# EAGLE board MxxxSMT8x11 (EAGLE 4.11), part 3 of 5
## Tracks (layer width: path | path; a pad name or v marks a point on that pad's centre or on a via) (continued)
GND4  (via drill 0.61) (continued)
  Bottom 0.381: 166.12,120.65 165.35,120.65 164.34,121.67 C100.2 163.32,122.17 157.99,122.17 C103.2 | 166.12,120.65 173.74,120.65 174.75,121.67 C96.2 175.77,121.67 176.02,121.41 179.07,121.41 179.83,120.65 187.96,120.65 188.09,120.78 | 224.66,120.78 224.54,120.65 214.88,120.65 214.76,120.78 | 224.66,120.78 225.55,121.67 C85.2 | 214.76,120.78 213.87,121.67 C88.2 | 200.79,120.78 200.91,120.65 214.63,120.65 214.76,120.78 | 200.79,120.78 199.9,121.67 C90.2 | 188.09,120.78 188.21,120.65 200.66,120.65 200.79,120.78 | 188.09,120.78 187.2,121.67 C93.2 | U$15.C2 242.57,118.62 240.54,120.65 224.79,120.65 224.66,120.78 | v175.51,73.91 183.64,73.91 R20.1 184.4,73.15 184.4,71.63 R17.1 | v241.55,77.47 240.54,78.49 224.03,78.49 223.77,78.74 v223.52,78.99 v214.63,78.99 214.38,78.74 v200.66,78.74 200.41,78.49 199.9,77.98 187.96,77.98 v187.71,77.72 187.45,77.98 187.2,78.23 177.29,78.23 177.04,78.49 165.1,78.49 161.54,82.04 160.27,82.04 v160.02,82.3 160.02,85.85 159,85.85 157.73,87.12 157.73,88.39 C105.2 157.99,89.15 163.32,89.15 C102.2 164.34,88.65 165.35,87.63 176.53,87.63 176.66,87.76 | C104.2 157.99,105.66 163.32,105.66 C101.2 164.34,105.16 165.35,104.14 173.74,104.14 174.75,105.16 C97.2 175.77,105.16 176.78,104.14 182.12,104.14 183.13,105.16 186.18,105.16 C94.2 187.2,105.16 188.21,104.14 197.87,104.14 198.88,105.16 C91.2 199.9,105.16 201.42,105.16 202.44,104.14 211.84,104.14 212.85,105.16 C89.2 213.87,105.16 214.88,104.14 218.95,104.14 219.46,104.65 225.04,104.65 225.55,105.16 C86.2 | C87.2 225.55,88.65 224.54,87.63 214.88,87.63 213.87,88.65 C99.2 212.85,88.65 212.34,88.14 205.49,88.14 204.98,87.63 198.12,87.63 197.99,87.76
  Bottom 0.381: 197.99,87.76 197.87,87.63 188.21,87.63 188.09,87.76 | 197.99,87.76 198.88,88.65 C92.2 | 188.09,87.76 187.2,88.65 C95.2 | 176.66,87.76 176.78,87.63 187.96,87.63 188.09,87.76 | 176.66,87.76 175.77,88.65 C98.2 | 166.12,120.65 166.12,117.35 162.56,117.35 v160.02,114.81
  pour Bottom: 240.03,128.27 240.03,66.04 129.54,66.04 129.54,128.27
  pour Top: 240.03,128.27 240.03,66.04 129.54,66.04 129.54,128.27
GND5  (via drill 0.61)
  Top 0.381: R24.1 184.4,8.13 184.4,11.68 185.17,12.45 E114.7 186.94,12.45 v187.71,11.68 | v175.51,7.87 175.51,12.45 E117.7 | v223.52,12.95 224.54,12.95 E120.7 | v214.63,12.95 213.61,12.95 E107.7 | v200.66,12.7 199.64,12.7 E111.7 | v241.55,11.43 242.57,11.43 U$18.T1 | E115.7 175.51,45.47 175.51,39.88 C118.2 | C122.2 163.83,39.88 163.83,45.47 E121.7 162.31,45.72 161.04,46.99 161.04,47.5 159.89,48.64 | 159.89,48.64 159.77,48.77 159.77,49.28 159,49.28 E124.11 | E118.7 226.31,45.47 226.31,39.88 C107.2 | E106.7 213.61,45.47 213.61,39.88 C110.2 213.61,38.86 215.65,36.83 215.65,30.73 213.61,28.7 | E109.7 199.39,45.47 199.39,39.88 C112.2 | E112.7 186.94,45.47 186.94,39.88 C115.2 | E119.7 226.06,28.96 226.06,23.37 C108.2 | 213.61,28.7 213.61,23.37 C120.2 | 213.61,28.7 213.61,28.96 E108.7 | E126.11 159,16.26 v160.02,16.26 160.27,16.26 160.27,13.97 161.29,12.95 162.31,12.95 E123.7 | E125.11 159,32.77 159.77,32.77 159.77,31.75 162.31,29.21 E122.7 164.08,28.96 164.08,23.37 C123.2 | E116.7 175.51,28.96 175.51,23.37 C119.2 | E110.7 199.39,28.96 199.39,23.37 C113.2 | E113.7 186.94,28.96 186.94,23.37 C116.2 | v160.02,48.77 159.89,48.64
  Bottom 0.381: 166.12,54.61 165.35,54.61 164.34,55.63 C121.2 163.32,56.13 157.99,56.13 C124.2 | 166.12,54.61 173.74,54.61 174.75,55.63 C117.2 175.77,55.63 176.02,55.37 179.07,55.37 179.83,54.61 187.96,54.61 188.09,54.74 | 224.66,54.74 224.54,54.61 214.88,54.61 214.76,54.74 | 224.66,54.74 225.55,55.63 C106.2 | 214.76,54.74 213.87,55.63 C109.2 | 200.79,54.74 200.91,54.61 214.63,54.61 214.76,54.74 | 200.79,54.74 199.9,55.63 C111.2 | 188.09,54.74 188.21,54.61 200.66,54.61 200.79,54.74 | 188.09,54.74 187.2,55.63 C114.2 | U$18.C2 242.57,52.58 240.54,54.61 224.79,54.61 224.66,54.74 | v175.51,7.87 183.64,7.87 R24.1 184.4,7.11 184.4,5.59 R21.1 | v241.55,11.43 240.54,12.45 224.03,12.45 223.77,12.7 v223.52,12.95 v214.63,12.95 214.38,12.7 v200.66,12.7 200.41,12.45 199.9,11.94 187.96,11.94 v187.71,11.68 187.45,11.94 187.2,12.19 177.29,12.19 177.04,12.45 165.1,12.45 161.54,16 160.27,16 v160.02,16.26 160.02,19.81 159,19.81 157.73,21.08 157.73,22.35 C126.2 157.99,23.11 163.32,23.11 C123.2 164.34,22.61 165.35,21.59 176.53,21.59 176.66,21.72 | C125.2 157.99,39.62 163.32,39.62 C122.2 164.34,39.12 165.35,38.1 173.74,38.1 174.75,39.12 C118.2 175.77,39.12 176.78,38.1 182.12,38.1 183.13,39.12 186.18,39.12 C115.2 187.2,39.12 188.21,38.1 197.87,38.1 198.88,39.12 C112.2 199.9,39.12 201.42,39.12 202.44,38.1 211.84,38.1 212.85,39.12 C110.2 213.87,39.12 214.88,38.1 218.95,38.1 219.46,38.61 225.04,38.61 225.55,39.12 C107.2 | C108.2 225.55,22.61 224.54,21.59 214.88,21.59 213.87,22.61 C120.2 212.85,22.61 212.34,22.1 205.49,22.1 204.98,21.59 198.12,21.59 197.99,21.72
  Bottom 0.381: 197.99,21.72 197.87,21.59 188.21,21.59 188.09,21.72 | 197.99,21.72 198.88,22.61 C113.2 | 188.09,21.72 187.2,22.61 C116.2 | 176.66,21.72 176.78,21.59 187.96,21.59 188.09,21.72 | 176.66,21.72 175.77,22.61 C119.2 | 166.12,54.61 166.12,51.31 162.56,51.31 v160.02,48.77
  pour Bottom: 240.03,62.23 240.03,0 129.54,0 129.54,62.23
  pour Top: 240.03,62.23 240.03,0 129.54,0 129.54,62.23
H1  (via drill 0.61)
  Top 0.254: E1.10 25.65,14.22 26.42,14.22 26.42,17.02 v23.88,19.56 21.08,22.35 13.97,22.35 U$1.H1 | E7.11 52.32,12.95 53.09,12.95 53.09,17.02 49.78,20.32 v48.51,20.32 47.24,20.32 46.48,19.56 v45.21,19.56 45.21,28.7 44.7,29.21 E5.4 | v62.23,21.34 v62.23,27.43 62.23,27.69 63.25,27.69 E11.12 | E17.3 92.46,27.69 89.92,27.69 89.92,23.62 v87.63,21.34 87.63,21.08 v87.63,18.54 | v98.04,18.54 98.04,19.3 103.89,25.15 E20.1 | v73.66,25.65 73.66,28.96 74.68,28.96 E14.11
  Bottom 0.254: v48.51,20.32 61.21,20.32 v62.23,21.34 62.48,21.08 68.83,21.08 69.09,20.83 87.12,20.83 v87.63,21.34 | v87.63,18.54 v98.04,18.54 | v73.66,25.65 72.14,25.65 70.36,27.43 v62.23,27.43 | v23.88,19.56 v45.21,19.56
H2  (via drill 0.61)
  Top 0.254: v68.58,14.22 69.6,14.22 E10.5 | E7.6 58.67,14.99 59.69,14.99 v59.69,14.73 59.94,14.48 60.71,13.72 v60.71,3.05 | 84.33,13.46 86.11,15.24 E16.9 87.88,15.49 v88.9,15.49 | 84.33,13.46 83.82,12.95 82.8,12.95 E13.4 | v100.33,15.24 99.31,15.24 E19.9 | v83.82,14.22 84.33,13.72 84.33,13.46 | 22.86,10.41 18.8,10.41 18.8,17.53 v16.76,19.56 | 22.86,10.41 23.88,10.41 E1.13 | v35.56,12.95 35.56,13.72 36.58,13.72 E4.10 | 22.86,10.41 v22.86,10.16 23.11,9.91 23.11,6.6 v24.38,5.33
  Bottom 0.254: v59.69,14.73 60.2,14.22 v68.58,14.22 68.83,14.22 v83.82,14.22 | v100.33,15.24 100.08,15.49 v88.9,15.49 | v16.76,19.56 13.97,22.35 U$1.H2 | v35.56,12.95 32.77,10.16 v22.86,10.16 | v60.71,3.05 26.67,3.05 v24.38,5.33
H3  (via drill 0.61)
  Top 0.254: v68.58,80.26 69.6,80.26 E28.5 | E25.6 58.67,81.03 59.69,81.03 v59.69,80.77 59.94,80.52 60.71,79.76 v60.71,69.09 | 84.33,79.5 86.11,81.28 E37.9 87.88,81.53 v88.9,81.53 | 84.33,79.5 83.82,78.99 82.8,78.99 E31.4 | v100.33,81.28 99.31,81.28 E40.9 | v83.82,80.26 84.33,79.76 84.33,79.5 | 22.86,76.45 18.8,76.45 18.8,83.57 v16.76,85.6 | 22.86,76.45 23.88,76.45 E34.13 | v35.56,78.99 35.56,79.76 36.58,79.76 E22.10 | 22.86,76.45 v22.86,76.2 23.11,75.95 23.11,72.64 v24.38,71.37
  Bottom 0.254: v59.69,80.77 60.2,80.26 v68.58,80.26 68.83,80.26 v83.82,80.26 | v100.33,81.28 100.08,81.53 v88.9,81.53 | v16.76,85.6 13.97,88.39 U$6.H2 | v35.56,78.99 32.77,76.2 v22.86,76.2 | v60.71,69.09 26.67,69.09 v24.38,71.37
H4  (via drill 0.61)
  Top 0.254: E34.10 25.65,80.26 26.42,80.26 26.42,83.06 v23.88,85.6 21.08,88.39 13.97,88.39 U$6.H1 | E25.11 52.32,78.99 53.09,78.99 53.09,83.06 49.78,86.36 v48.51,86.36 47.24,86.36 46.48,85.6 v45.21,85.6 45.21,94.74 44.7,95.25 E24.4 | v62.23,87.38 v62.23,93.47 62.23,93.73 63.25,93.73 E29.12 | E38.3 92.46,93.73 89.92,93.73 89.92,89.66 v87.63,87.38 87.63,87.12 v87.63,84.58 | v98.04,84.58 98.04,85.34 103.89,91.19 E41.1 | v73.66,91.69 73.66,95 74.68,95 E32.11
  Bottom 0.254: v48.51,86.36 61.21,86.36 v62.23,87.38 62.48,87.12 68.83,87.12 69.09,86.87 87.12,86.87 v87.63,87.38 | v87.63,84.58 v98.04,84.58 | v73.66,91.69 72.14,91.69 70.36,93.47 v62.23,93.47 | v23.88,85.6 v45.21,85.6
H5  (via drill 0.61)
  Top 0.254: v68.58,146.3 69.6,146.3 E49.5 | E46.6 58.67,147.07 59.69,147.07 v59.69,146.81 59.94,146.56 60.71,145.8 v60.71,135.13 | 84.33,145.54 86.11,147.32 E58.9 87.88,147.57 v88.9,147.57 | 84.33,145.54 83.82,145.03 82.8,145.03 E52.4 | v100.33,147.32 99.31,147.32 E61.9 | v83.82,146.3 84.33,145.8 84.33,145.54 | 22.86,142.49 18.8,142.49 18.8,149.61 v16.76,151.64 | 22.86,142.49 23.88,142.49 E55.13 | v35.56,145.03 35.56,145.8 36.58,145.8 E43.10 | 22.86,142.49 v22.86,142.24 23.11,141.99 23.11,138.68 v24.38,137.41
  Bottom 0.254: v59.69,146.81 60.2,146.3 v68.58,146.3 68.83,146.3 v83.82,146.3 | v100.33,147.32 100.08,147.57 v88.9,147.57 | v16.76,151.64 13.97,154.43 U$9.H2 | v35.56,145.03 32.77,142.24 v22.86,142.24 | v60.71,135.13 26.67,135.13 v24.38,137.41
H6  (via drill 0.61)
  Top 0.254: E55.10 25.65,146.3 26.42,146.3 26.42,149.1 v23.88,151.64 21.08,154.43 13.97,154.43 U$9.H1 | E46.11 52.32,145.03 53.09,145.03 53.09,149.1 49.78,152.4 v48.51,152.4 47.24,152.4 46.48,151.64 v45.21,151.64 45.21,160.78 44.7,161.29 E45.4 | v62.23,153.42 v62.23,159.51 62.23,159.77 63.25,159.77 E50.12 | E59.3 92.46,159.77 89.92,159.77 89.92,155.7 v87.63,153.42 87.63,153.16 v87.63,150.62 | v98.04,150.62 98.04,151.38 103.89,157.23 E62.1 | v73.66,157.73 73.66,161.04 74.68,161.04 E53.11
  Bottom 0.254: v48.51,152.4 61.21,152.4 v62.23,153.42 62.48,153.16 68.83,153.16 69.09,152.91 87.12,152.91 v87.63,153.42 | v98.04,150.62 v87.63,150.62 | v73.66,157.73 72.14,157.73 70.36,159.51 v62.23,159.51 | v45.21,151.64 v23.88,151.64
H7  (via drill 0.61)
  Top 0.254: v187.96,180.09 186.94,180.09 E70.5 | E67.6 197.87,179.32 196.85,179.32 v196.85,179.58 196.6,179.83 195.83,180.59 v195.83,191.26 | 172.21,180.85 170.43,179.07 E79.9 168.66,178.82 v167.64,178.82 | 172.21,180.85 172.72,181.36 173.74,181.36 E73.4 | v156.21,179.07 157.23,179.07 E82.9 | v172.72,180.09 172.21,180.59 172.21,180.85 | 233.68,183.9 237.74,183.9 237.74,176.78 v239.78,174.75 | 233.68,183.9 232.66,183.9 E76.13 | v220.98,181.36 220.98,180.59 219.96,180.59 E64.10 | 233.68,183.9 v233.68,184.15 233.43,184.4 233.43,187.71 v232.16,188.98
  Bottom 0.254: v196.85,179.58 196.34,180.09 v187.96,180.09 187.71,180.09 v172.72,180.09 | v156.21,179.07 156.46,178.82 v167.64,178.82 | v239.78,174.75 242.57,171.96 U$12.H2 | v220.98,181.36 223.77,184.15 v233.68,184.15 | v195.83,191.26 229.87,191.26 v232.16,188.98
H8  (via drill 0.61)
  Top 0.254: E76.10 230.89,180.09 230.12,180.09 230.12,177.29 v232.66,174.75 235.46,171.96 242.57,171.96 U$12.H1 | E67.11 204.22,181.36 203.45,181.36 203.45,177.29 206.76,173.99 v208.03,173.99 209.3,173.99 210.06,174.75 v211.33,174.75 211.33,165.61 211.84,165.1 E66.4 | v194.31,172.97 v194.31,166.88 194.31,166.62 193.29,166.62 E71.12 | E80.3 164.08,166.62 166.62,166.62 166.62,170.69 v168.91,172.97 168.91,173.23 v168.91,175.77 | v158.5,175.77 158.5,175.01 152.65,169.16 E83.1 | v182.88,168.66 182.88,165.35 181.86,165.35 E74.11
  Bottom 0.254: v208.03,173.99 195.33,173.99 v194.31,172.97 194.06,173.23 187.71,173.23 187.45,173.48 169.42,173.48 v168.91,172.97 | v158.5,175.77 v168.91,175.77 | v182.88,168.66 184.4,168.66 186.18,166.88 v194.31,166.88 | v211.33,174.75 v232.66,174.75
H9  (via drill 0.61)
  Top 0.254: v187.96,114.05 186.94,114.05 E91.5 | E88.6 197.87,113.28 196.85,113.28 v196.85,113.54 196.6,113.79 195.83,114.55 v195.83,125.22 | 172.21,114.81 170.43,113.03 E100.9 168.66,112.78 v167.64,112.78 | 172.21,114.81 172.72,115.32 173.74,115.32 E94.4 | v156.21,113.03 157.23,113.03 E103.9 | v172.72,114.05 172.21,114.55 172.21,114.81 | 233.68,117.86 237.74,117.86 237.74,110.74 v239.78,108.71 | 233.68,117.86 232.66,117.86 E97.13 | v220.98,115.32 220.98,114.55 219.96,114.55 E85.10 | 233.68,117.86 v233.68,118.11 233.43,118.36 233.43,121.67 v232.16,122.94
  Bottom 0.254: v196.85,113.54 196.34,114.05 v187.96,114.05 187.71,114.05 v172.72,114.05 | v156.21,113.03 156.46,112.78 v167.64,112.78 | v239.78,108.71 242.57,105.92 U$15.H2 | v220.98,115.32 223.77,118.11 v233.68,118.11 | v195.83,125.22 229.87,125.22 v232.16,122.94
H10  (via drill 0.61)
  Top 0.254: E97.10 230.89,114.05 230.12,114.05 230.12,111.25 v232.66,108.71 235.46,105.92 242.57,105.92 U$15.H1 | E88.11 204.22,115.32 203.45,115.32 203.45,111.25 206.76,107.95 v208.03,107.95 209.3,107.95 210.06,108.71 v211.33,108.71 211.33,99.57 211.84,99.06 E87.4 | v194.31,106.93 v194.31,100.84 194.31,100.58 193.29,100.58 E92.12 | E101.3 164.08,100.58 166.62,100.58 166.62,104.65 v168.91,106.93 168.91,107.19 v168.91,109.73 | v158.5,109.73 158.5,108.97 152.65,103.12 E104.1 | v182.88,102.62 182.88,99.31 181.86,99.31 E95.11
  Bottom 0.254: v208.03,107.95 195.33,107.95 v194.31,106.93 194.06,107.19 187.71,107.19 187.45,107.44 169.42,107.44 v168.91,106.93 | v158.5,109.73 v168.91,109.73 | v182.88,102.62 184.4,102.62 186.18,100.84 v194.31,100.84 | v211.33,108.71 v232.66,108.71
H11  (via drill 0.61)
  Top 0.254: v187.96,48.01 186.94,48.01 E112.5 | E109.6 197.87,47.24 196.85,47.24 v196.85,47.5 196.6,47.75 195.83,48.51 v195.83,59.18 | 172.21,48.77 170.43,46.99 E121.9 168.66,46.74 v167.64,46.74 | 172.21,48.77 172.72,49.28 173.74,49.28 E115.4 | v156.21,46.99 157.23,46.99 E124.9 | v172.72,48.01 172.21,48.51 172.21,48.77 | 233.68,51.82 237.74,51.82 237.74,44.7 v239.78,42.67 | 233.68,51.82 232.66,51.82 E118.13 | v220.98,49.28 220.98,48.51 219.96,48.51 E106.10 | 233.68,51.82 v233.68,52.07 233.43,52.32 233.43,55.63 v232.16,56.9
  Bottom 0.254: v196.85,47.5 196.34,48.01 v187.96,48.01 187.71,48.01 v172.72,48.01 | v156.21,46.99 156.46,46.74 v167.64,46.74 | v239.78,42.67 242.57,39.88 U$18.H2 | v220.98,49.28 223.77,52.07 v233.68,52.07 | v195.83,59.18 229.87,59.18 v232.16,56.9
H12  (via drill 0.61)
  Top 0.254: E118.10 230.89,48.01 230.12,48.01 230.12,45.21 v232.66,42.67 235.46,39.88 242.57,39.88 U$18.H1 | E109.11 204.22,49.28 203.45,49.28 203.45,45.21 206.76,41.91 v208.03,41.91 209.3,41.91 210.06,42.67 v211.33,42.67 211.33,33.53 211.84,33.02 E108.4 | v194.31,40.89 v194.31,34.8 194.31,34.54 193.29,34.54 E113.12 | E122.3 164.08,34.54 166.62,34.54 166.62,38.61 v168.91,40.89 168.91,41.15 v168.91,43.69 | v158.5,43.69 158.5,42.93 152.65,37.08 E125.1 | v182.88,36.58 182.88,33.27 181.86,33.27 E116.11
  Bottom 0.254: v208.03,41.91 195.33,41.91 v194.31,40.89 194.06,41.15 187.71,41.15 187.45,41.4 169.42,41.4 v168.91,40.89 | v168.91,43.69 v158.5,43.69 | v182.88,36.58 184.4,36.58 186.18,34.8 v194.31,34.8 | v232.66,42.67 v211.33,42.67
J1  (via drill 0.61)
  Top 0.254: v95.25,26.42 94.23,26.42 E17.2 | v102.87,27.43 103.89,27.43 103.89,27.69 E20.3 | 66.04,30.23 65.02,30.23 E11.10 | 66.04,30.23 v66.04,28.96 | E14.5 81.03,30.48 v80.01,29.46 79.76,29.21 78.99,28.45 v78.99,25.65 | v29.21,25.4 30.23,25.4 E2.1 | v14.99,25.15 13.97,26.16 U$1.J1 | v49.78,17.53 50.55,16.76 E7.8 | 45.72,30.23 46.23,30.23 v46.23,20.57 | 45.72,30.23 44.7,30.23 E5.5 | v66.04,32.26 66.04,30.23 | 45.72,30.23 v45.72,33.53
  Bottom 0.254: v95.25,26.42 96.01,27.18 97.28,27.18 | 97.28,27.18 102.62,27.18 v102.87,27.43 | v66.04,28.96 66.55,29.46 v80.01,29.46 | 97.28,27.18 97.28,31.24 95,31.24 89.41,25.65 v78.99,25.65 | v29.21,25.4 28.96,25.15 21.59,25.15 | v14.99,25.15 21.59,25.15 | v49.78,17.53 46.48,20.83 46.23,20.83 | 46.23,20.83 25.91,20.83 21.59,25.15 | 46.23,20.83 v46.23,20.57 | v66.04,32.26 65.53,31.75 57.91,31.75 55.63,34.04 46.23,34.04 v45.72,33.53
J2  (via drill 0.61)
  Top 0.254: 72.64,15.49 74.17,15.49 74.17,16 74.68,16.51 E13.8 76.45,16.76 76.45,19.56 80.77,23.88 80.77,24.13 81.53,24.13 82.55,23.11 82.55,20.32 86.11,16.76 E16.8 87.88,16.76 88.65,17.53 88.65,20.83 90.42,22.61 90.42,24.64 93.22,24.64 94.49,23.37 94.49,19.81 97.54,16.76 E19.8 | 72.64,15.49 71.37,15.49 E10.6 | 26.92,11.68 25.65,11.68 E1.12 | 26.92,11.68 26.92,17.78 24.38,20.32 | 24.38,20.32 v18.54,26.16 | 24.38,20.32 26.67,22.61 26.67,24.13 v29.72,24.13 30.73,24.13 33.78,21.08 33.78,15.49 36.58,15.49 E4.9 | v54.86,27.18 54.86,27.69 56.9,27.69 E8.3 | 72.64,15.49 72.64,9.91 73.41,9.14 v73.41,5.33 | v27.94,4.06 26.92,5.08 26.92,11.68
  Bottom 0.254: v18.54,26.16 13.97,26.16 U$1.J2 | v54.86,27.18 53.34,25.65 31.24,25.65 v29.72,24.13 | v73.41,5.33 72.14,4.06 v27.94,4.06
J3  (via drill 0.61)
  Top 0.254: 72.64,81.53 74.17,81.53 74.17,82.04 74.68,82.55 E31.8 76.45,82.8 76.45,85.6 80.77,89.92 80.77,90.17 81.53,90.17 82.55,89.15 82.55,86.36 86.11,82.8 E37.8 87.88,82.8 88.65,83.57 88.65,86.87 90.42,88.65 90.42,90.68 93.22,90.68 94.49,89.41 94.49,85.85 97.54,82.8 E40.8 | 72.64,81.53 71.37,81.53 E28.6 | 26.92,77.72 25.65,77.72 E34.12 | 26.92,77.72 26.92,83.82 24.38,86.36 | 24.38,86.36 v18.54,92.2 | 24.38,86.36 26.67,88.65 26.67,90.17 v29.72,90.17 30.73,90.17 33.78,87.12 33.78,81.53 36.58,81.53 E22.9 | v54.86,93.22 54.86,93.73 56.9,93.73 E26.3 | 72.64,81.53 72.64,75.95 73.41,75.18 v73.41,71.37 | v27.94,70.1 26.92,71.12 26.92,77.72
  Bottom 0.254: v18.54,92.2 13.97,92.2 U$6.J2 | v54.86,93.22 53.34,91.69 31.24,91.69 v29.72,90.17 | v73.41,71.37 72.14,70.1 v27.94,70.1
J4  (via drill 0.61)
  Top 0.254: v95.25,92.46 94.23,92.46 E38.2 | v102.87,93.47 103.89,93.47 103.89,93.73 E41.3 | 66.04,96.27 65.02,96.27 E29.10 | 66.04,96.27 v66.04,95 | E32.5 81.03,96.52 v80.01,95.5 79.76,95.25 78.99,94.49 v78.99,91.69 | v29.21,91.44 30.23,91.44 E35.1 | v14.99,91.19 13.97,92.2 U$6.J1 | v49.78,83.57 50.55,82.8 E25.8 | 45.72,96.27 46.23,96.27 v46.23,86.61 | 45.72,96.27 44.7,96.27 E24.5 | v66.04,98.3 66.04,96.27 | 45.72,96.27 v45.72,99.57
  Bottom 0.254: v95.25,92.46 96.01,93.22 97.28,93.22 | 97.28,93.22 102.62,93.22 v102.87,93.47 | v66.04,95 66.55,95.5 v80.01,95.5 | 97.28,93.22 97.28,97.28 95,97.28 89.41,91.69 v78.99,91.69 | v29.21,91.44 28.96,91.19 21.59,91.19 | v14.99,91.19 21.59,91.19 | v49.78,83.57 46.48,86.87 46.23,86.87 | 46.23,86.87 25.91,86.87 21.59,91.19 | 46.23,86.87 v46.23,86.61 | v66.04,98.3 65.53,97.79 57.91,97.79 55.63,100.08 46.23,100.08 v45.72,99.57
J5  (via drill 0.61)
  Top 0.254: 72.64,147.57 74.17,147.57 74.17,148.08 74.68,148.59 E52.8 76.45,148.84 76.45,151.64 80.77,155.96 80.77,156.21 81.53,156.21 82.55,155.19 82.55,152.4 86.11,148.84 E58.8 87.88,148.84 88.65,149.61 88.65,152.91 90.42,154.69 90.42,156.72 93.22,156.72 94.49,155.45 94.49,151.89 97.54,148.84 E61.8 | 72.64,147.57 71.37,147.57 E49.6 | 26.92,143.76 25.65,143.76 E55.12 | 26.92,143.76 26.92,149.86 24.38,152.4 | 24.38,152.4 v18.54,158.24 | 24.38,152.4 26.67,154.69 26.67,156.21 v29.72,156.21 30.73,156.21 33.78,153.16 33.78,147.57 36.58,147.57 E43.9 | v54.86,159.26 54.86,159.77 56.9,159.77 E47.3 | 72.64,147.57 72.64,141.99 73.41,141.22 v73.41,137.41 | v27.94,136.14 26.92,137.16 26.92,143.76
  Bottom 0.254: v18.54,158.24 13.97,158.24 U$9.J2 | v54.86,159.26 53.34,157.73 31.24,157.73 v29.72,156.21 | v73.41,137.41 72.14,136.14 v27.94,136.14
J6  (via drill 0.61)
  Top 0.254: v95.25,158.5 94.23,158.5 E59.2 | v102.87,159.51 103.89,159.51 103.89,159.77 E62.3 | 66.04,162.31 65.02,162.31 E50.10 | v66.04,161.04 66.04,162.31 | E53.5 81.03,162.56 v80.01,161.54 79.76,161.29 78.99,160.53 v78.99,157.73 | v29.21,157.48 30.23,157.48 E56.1 | v14.99,157.23 13.97,158.24 U$9.J1 | v49.78,149.61 50.55,148.84 E46.8 | 45.72,162.31 46.23,162.31 v46.23,152.65 | 45.72,162.31 44.7,162.31 E45.5 | 66.04,162.31 v66.04,164.34 | v45.72,165.61 45.72,162.31
  Bottom 0.254: v95.25,158.5 96.01,159.26 97.28,159.26 | 97.28,159.26 102.62,159.26 v102.87,159.51 | v66.04,161.04 66.55,161.54 v80.01,161.54 | 97.28,159.26 97.28,163.32 95,163.32 89.41,157.73 v78.99,157.73 | v29.21,157.48 28.96,157.23 21.59,157.23 | 21.59,157.23 v14.99,157.23 | v49.78,149.61 46.48,152.91 46.23,152.91 | 46.23,152.91 25.91,152.91 21.59,157.23 | v46.23,152.65 46.23,152.91 | v66.04,164.34 65.53,163.83 57.91,163.83 55.63,166.12 46.23,166.12 v45.72,165.61
J7  (via drill 0.61)
  Top 0.254: 183.9,178.82 182.37,178.82 182.37,178.31 181.86,177.8 E73.8 180.09,177.55 180.09,174.75 175.77,170.43 175.77,170.18 175.01,170.18 173.99,171.2 173.99,173.99 170.43,177.55 E79.8 168.66,177.55 167.89,176.78 167.89,173.48 166.12,171.7 166.12,169.67 163.32,169.67 162.05,170.94 162.05,174.5 159,177.55 E82.8 | 183.9,178.82 185.17,178.82 E70.6 | 229.62,182.63 230.89,182.63 E76.12 | 229.62,182.63 229.62,176.53 232.16,173.99 | 232.16,173.99 v238,168.15 | 232.16,173.99 229.87,171.7 229.87,170.18 v226.82,170.18 225.81,170.18 222.76,173.23 222.76,178.82 219.96,178.82 E64.9 | v201.68,167.13 201.68,166.62 199.64,166.62 E68.3 | 183.9,178.82 183.9,184.4 183.13,185.17 v183.13,188.98 | v228.6,190.25 229.62,189.23 229.62,182.63
  Bottom 0.254: v238,168.15 242.57,168.15 U$12.J2 | v201.68,167.13 203.2,168.66 225.3,168.66 v226.82,170.18 | v183.13,188.98 184.4,190.25 v228.6,190.25
J8  (via drill 0.61)
  Top 0.254: v161.29,167.89 162.31,167.89 E80.2 | v153.67,166.88 152.65,166.88 152.65,166.62 E83.3 | 190.5,164.08 191.52,164.08 E71.10 | v190.5,165.35 190.5,164.08 | E74.5 175.51,163.83 v176.53,164.85 176.78,165.1 177.55,165.86 v177.55,168.66 | v227.33,168.91 226.31,168.91 E77.1 | v241.55,169.16 242.57,168.15 U$12.J1 | v206.76,176.78 205.99,177.55 E67.8 | 210.82,164.08 210.31,164.08 v210.31,173.74 | 210.82,164.08 211.84,164.08 E66.5 | 190.5,164.08 v190.5,162.05 | v210.82,160.78 210.82,164.08
  Bottom 0.254: v161.29,167.89 160.53,167.13 159.26,167.13 | 159.26,167.13 153.92,167.13 v153.67,166.88 | v190.5,165.35 189.99,164.85 v176.53,164.85 | 159.26,167.13 159.26,163.07 161.54,163.07 167.13,168.66 v177.55,168.66 | v227.33,168.91 227.58,169.16 234.95,169.16 | 234.95,169.16 v241.55,169.16 | v206.76,176.78 210.06,173.48 210.31,173.48 | 210.31,173.48 230.63,173.48 234.95,169.16 | v210.31,173.74 210.31,173.48 | v190.5,162.05 191.01,162.56 198.63,162.56 200.91,160.27 210.31,160.27 v210.82,160.78
J9  (via drill 0.61)
  Top 0.254: 183.9,112.78 182.37,112.78 182.37,112.27 181.86,111.76 E94.8 180.09,111.51 180.09,108.71 175.77,104.39 175.77,104.14 175.01,104.14 173.99,105.16 173.99,107.95 170.43,111.51 E100.8 168.66,111.51 167.89,110.74 167.89,107.44 166.12,105.66 166.12,103.63 163.32,103.63 162.05,104.9 162.05,108.46 159,111.51 E103.8 | 183.9,112.78 185.17,112.78 E91.6 | 229.62,116.59 230.89,116.59 E97.12 | 229.62,116.59 229.62,110.49 232.16,107.95 | 232.16,107.95 v238,102.11 | 232.16,107.95 229.87,105.66 229.87,104.14 v226.82,104.14 225.81,104.14 222.76,107.19 222.76,112.78 219.96,112.78 E85.9 | v201.68,101.09 201.68,100.58 199.64,100.58 E89.3 | 183.9,112.78 183.9,118.36 183.13,119.13 v183.13,122.94 | v228.6,124.21 229.62,123.19 229.62,116.59
  Bottom 0.254: v238,102.11 242.57,102.11 U$15.J2 | v201.68,101.09 203.2,102.62 225.3,102.62 v226.82,104.14 | v183.13,122.94 184.4,124.21 v228.6,124.21
J10  (via drill 0.61)
  Top 0.254: v161.29,101.85 162.31,101.85 E101.2 | v153.67,100.84 152.65,100.84 152.65,100.58 E104.3 | 190.5,98.04 191.52,98.04 E92.10 | v190.5,99.31 190.5,98.04 | E95.5 175.51,97.79 v176.53,98.81 176.78,99.06 177.55,99.82 v177.55,102.62 | v227.33,102.87 226.31,102.87 E98.1 | v241.55,103.12 242.57,102.11 U$15.J1 | v206.76,110.74 205.99,111.51 E88.8 | 210.82,98.04 210.31,98.04 v210.31,107.7 | 210.82,98.04 211.84,98.04 E87.5 | 190.5,98.04 v190.5,96.01 | v210.82,94.74 210.82,98.04
  Bottom 0.254: v161.29,101.85 160.53,101.09 159.26,101.09 | 159.26,101.09 153.92,101.09 v153.67,100.84 | v190.5,99.31 189.99,98.81 v176.53,98.81 | 159.26,101.09 159.26,97.03 161.54,97.03 167.13,102.62 v177.55,102.62 | v227.33,102.87 227.58,103.12 234.95,103.12 | 234.95,103.12 v241.55,103.12 | v206.76,110.74 210.06,107.44 210.31,107.44 | 210.31,107.44 230.63,107.44 234.95,103.12 | v210.31,107.7 210.31,107.44 | v190.5,96.01 191.01,96.52 198.63,96.52 200.91,94.23 210.31,94.23 v210.82,94.74
J11  (via drill 0.61)
  Top 0.254: 183.9,46.74 182.37,46.74 182.37,46.23 181.86,45.72 E115.8 180.09,45.47 180.09,42.67 175.77,38.35 175.77,38.1 175.01,38.1 173.99,39.12 173.99,41.91 170.43,45.47 E121.8 168.66,45.47 167.89,44.7 167.89,41.4 166.12,39.62 166.12,37.59 163.32,37.59 162.05,38.86 162.05,42.42 159,45.47 E124.8 | 183.9,46.74 185.17,46.74 E112.6 | 229.62,50.55 230.89,50.55 E118.12 | 229.62,50.55 229.62,44.45 232.16,41.91 | 232.16,41.91 v238,36.07 | 232.16,41.91 229.87,39.62 229.87,38.1 v226.82,38.1 225.81,38.1 222.76,41.15 222.76,46.74 219.96,46.74 E106.9 | v201.68,35.05 201.68,34.54 199.64,34.54 E110.3 | 183.9,46.74 183.9,52.32 183.13,53.09 v183.13,56.9 | v228.6,58.17 229.62,57.15 229.62,50.55
  Bottom 0.254: v238,36.07 242.57,36.07 U$18.J2 | v201.68,35.05 203.2,36.58 225.3,36.58 v226.82,38.1 | v183.13,56.9 184.4,58.17 v228.6,58.17
J12  (via drill 0.61)
  Top 0.254: v161.29,35.81 162.31,35.81 E122.2 | v153.67,34.8 152.65,34.8 152.65,34.54 E125.3 | 190.5,32 191.52,32 E113.10 | 190.5,32 v190.5,33.27 | E116.5 175.51,31.75 v176.53,32.77 176.78,33.02 177.55,33.78 v177.55,36.58 | v227.33,36.83 226.31,36.83 E119.1 | v241.55,37.08 242.57,36.07 U$18.J1 | v206.76,44.7 205.99,45.47 E109.8 | 210.82,32 210.31,32 v210.31,41.66 | 210.82,32 211.84,32 E108.5 | v190.5,29.97 190.5,32 | 210.82,32 v210.82,28.7
  Bottom 0.254: v161.29,35.81 160.53,35.05 159.26,35.05 | 159.26,35.05 153.92,35.05 v153.67,34.8 | v190.5,33.27 189.99,32.77 v176.53,32.77 | 159.26,35.05 159.26,30.99 161.54,30.99 167.13,36.58 v177.55,36.58 | v227.33,36.83 227.58,37.08 234.95,37.08 | 234.95,37.08 v241.55,37.08 | v206.76,44.7 210.06,41.4 210.31,41.4 | 210.31,41.4 230.63,41.4 234.95,37.08 | 210.31,41.4 v210.31,41.66 | v190.5,29.97 191.01,30.48 198.63,30.48 200.91,28.19 210.31,28.19 v210.82,28.7
K1  (via drill 0.61)
  Top 0.254: E20.14 97.54,25.4 95.5,27.43 95.5,28.96 94.23,28.96 E17.4 92.46,29.46 91.19,29.46 91.19,32.26 90.93,32.51 90.93,34.29 89.92,35.31 86.11,35.31 85.34,36.07 83.31,36.07 83.31,32.26 82.8,31.75 E14.6 81.03,31.75 v80.01,31.75 | v29.21,26.92 30.23,26.92 E2.2 | v14.73,27.94 13.97,28.7 U$1.K1 | v41.91,28.45 41.91,31.5 42.93,31.5 E5.6 | v55.88,25.65 56.9,25.65 E8.1 | v62.23,29.72 62.23,31.5 63.25,31.5 E11.9
  Bottom 0.254: v14.73,27.94 28.19,27.94 v29.21,26.92 29.46,27.18 30.23,27.94 41.4,27.94 v41.91,28.45 42.16,28.19 55.88,28.19 | 55.88,28.19 v55.88,25.65 | 55.88,28.19 56.39,28.7 61.21,28.7 v62.23,29.72 62.48,29.97 68.07,29.97 69.85,31.75 v80.01,31.75
K2  (via drill 0.61)
  Top 0.254: 106.17,36.83 106.17,42.67 105.66,43.18 E21.2 | 106.17,36.83 106.17,32 105.66,32 E20.6 | E18.13 87.88,43.43 90.17,43.43 90.42,43.69 90.93,43.69 91.69,42.93 91.69,42.67 92.46,41.91 E18.1 94.23,41.66 v98.81,37.08 | v102.87,48.51 103.89,48.51 E21.6 | K2B.1 86.61,56.39 87.63,55.37 87.63,53.85 86.61,52.83 K2A.1 | v105.92,36.83 106.17,36.83 | 85.6,26.16 85.6,25.65 82.8,25.65 E14.1 81.03,25.15 77.47,21.59 71.37,21.59 71.37,25.15 E11.1 69.6,25.15 v68.58,25.15 | 85.6,26.16 86.11,26.67 E17.13 | v59.69,27.69 59.69,28.96 58.67,28.96 E8.4 | 34.29,24.64 34.29,25.65 32,27.94 E2.3 30.23,28.19 v29.21,28.19 | 34.29,24.64 34.29,19.05 36.58,16.76 E4.8 | 34.29,24.64 v34.54,24.64 | v85.09,35.05 85.6,34.54 85.6,26.16
  Bottom 0.254: K2A.1 87.12,51.82 88.14,50.8 91.44,50.8 92.96,49.28 102.11,49.28 v102.87,48.51 103.12,48.26 108.2,48.26 108.2,37.59 107.44,36.83 v105.92,36.83 99.06,36.83 v98.81,37.08 98.55,36.83 96.77,35.05 v85.09,35.05 | v68.58,25.15 62.23,25.15 v59.69,27.69 59.44,27.43 56.64,24.64 54.61,24.64 54.36,24.89 34.8,24.89 v34.54,24.64 | v29.21,28.19 28.45,28.96 13.97,28.96 U$1.K2
K3  (via drill 0.61)
  Top 0.254: 106.17,102.87 106.17,108.71 105.66,109.22 E42.2 | 106.17,102.87 106.17,98.04 105.66,98.04 E41.6 | E39.13 87.88,109.47 90.17,109.47 90.42,109.73 90.93,109.73 91.69,108.97 91.69,108.71 92.46,107.95 E39.1 94.23,107.7 v98.81,103.12 | v102.87,114.55 103.89,114.55 E42.6 | K2B1.1 86.61,122.43 87.63,121.41 87.63,119.89 86.61,118.87 K2A1.1 | v105.92,102.87 106.17,102.87 | 85.6,92.2 85.6,91.69 82.8,91.69 E32.1 81.03,91.19 77.47,87.63 71.37,87.63 71.37,91.19 E29.1 69.6,91.19 v68.58,91.19 | 85.6,92.2 86.11,92.71 E38.13 | v59.69,93.73 59.69,95 58.67,95 E26.4 | 34.29,90.68 34.29,91.69 32,93.98 E35.3 30.23,94.23 v29.21,94.23 | 34.29,90.68 34.29,85.09 36.58,82.8 E22.8 | 34.29,90.68 v34.54,90.68 | v85.09,101.09 85.6,100.58 85.6,92.2
  Bottom 0.254: K2A1.1 87.12,117.86 88.14,116.84 91.44,116.84 92.96,115.32 102.11,115.32 v102.87,114.55 103.12,114.3 108.2,114.3 108.2,103.63 107.44,102.87 v105.92,102.87 99.06,102.87 v98.81,103.12 98.55,102.87 96.77,101.09 v85.09,101.09 | v68.58,91.19 62.23,91.19 v59.69,93.73 59.44,93.47 56.64,90.68 54.61,90.68 54.36,90.93 34.8,90.93 v34.54,90.68 | v29.21,94.23 28.45,95 13.97,95 U$6.K2
K4  (via drill 0.61)
  Top 0.254: E41.14 97.54,91.44 95.5,93.47 95.5,95 94.23,95 E38.4 92.46,95.5 91.19,95.5 91.19,98.3 90.93,98.55 90.93,100.33 89.92,101.35 86.11,101.35 85.34,102.11 83.31,102.11 83.31,98.3 82.8,97.79 E32.6 81.03,97.79 v80.01,97.79 | v29.21,92.96 30.23,92.96 E35.2 | v14.73,93.98 13.97,94.74 U$6.K1 | v41.91,94.49 41.91,97.54 42.93,97.54 E24.6 | v55.88,91.69 56.9,91.69 E26.1 | v62.23,95.76 62.23,97.54 63.25,97.54 E29.9
  Bottom 0.254: v14.73,93.98 28.19,93.98 v29.21,92.96 29.46,93.22 30.23,93.98 41.4,93.98 v41.91,94.49 42.16,94.23 55.88,94.23 | 55.88,94.23 v55.88,91.69 | 55.88,94.23 56.39,94.74 61.21,94.74 v62.23,95.76 62.48,96.01 68.07,96.01 69.85,97.79 v80.01,97.79
K5  (via drill 0.61)
  Top 0.254: 106.17,168.91 106.17,174.75 105.66,175.26 E63.2 | 106.17,168.91 106.17,164.08 105.66,164.08 E62.6 | E60.13 87.88,175.51 90.17,175.51 90.42,175.77 90.93,175.77 91.69,175.01 91.69,174.75 92.46,173.99 E60.1 94.23,173.74 v98.81,169.16 | v102.87,180.59 103.89,180.59 E63.6 | K2B2.1 86.61,188.47 87.63,187.45 87.63,185.93 86.61,184.91 K2A2.1 | v105.92,168.91 106.17,168.91 | 85.6,158.24 85.6,157.73 82.8,157.73 E53.1 81.03,157.23 77.47,153.67 71.37,153.67 71.37,157.23 E50.1 69.6,157.23 v68.58,157.23 | 85.6,158.24 86.11,158.75 E59.13 | v59.69,159.77 59.69,161.04 58.67,161.04 E47.4 | 34.29,156.72 34.29,157.73 32,160.02 E56.3 30.23,160.27 v29.21,160.27 | 34.29,156.72 34.29,151.13 36.58,148.84 E43.8 | v34.54,156.72 34.29,156.72 | v85.09,167.13 85.6,166.62 85.6,158.24
  Bottom 0.254: K2A2.1 87.12,183.9 88.14,182.88 91.44,182.88 92.96,181.36 102.11,181.36 v102.87,180.59 103.12,180.34 108.2,180.34 108.2,169.67 107.44,168.91 v105.92,168.91 99.06,168.91 v98.81,169.16 98.55,168.91 96.77,167.13 v85.09,167.13 | v68.58,157.23 62.23,157.23 v59.69,159.77 59.44,159.51 56.64,156.72 54.61,156.72 54.36,156.97 34.8,156.97 v34.54,156.72 | v29.21,160.27 28.45,161.04 13.97,161.04 U$9.K2
K6  (via drill 0.61)
  Top 0.254: E62.14 97.54,157.48 95.5,159.51 95.5,161.04 94.23,161.04 E59.4 92.46,161.54 91.19,161.54 91.19,164.34 90.93,164.59 90.93,166.37 89.92,167.39 86.11,167.39 85.34,168.15 83.31,168.15 83.31,164.34 82.8,163.83 E53.6 81.03,163.83 v80.01,163.83 | v29.21,159 30.23,159 E56.2 | v14.73,160.02 13.97,160.78 U$9.K1 | v41.91,160.53 41.91,163.58 42.93,163.58 E45.6 | v55.88,157.73 56.9,157.73 E47.1 | v62.23,161.8 62.23,163.58 63.25,163.58 E50.9
  Bottom 0.254: v14.73,160.02 28.19,160.02 v29.21,159 29.46,159.26 30.23,160.02 41.4,160.02 v41.91,160.53 42.16,160.27 55.88,160.27 | 55.88,160.27 v55.88,157.73 | 55.88,160.27 56.39,160.78 61.21,160.78 v62.23,161.8 62.48,162.05 68.07,162.05 69.85,163.83 v80.01,163.83
K7  (via drill 0.61)
  Top 0.254: 150.37,157.48 150.37,151.64 150.88,151.13 E84.2 | 150.37,157.48 150.37,162.31 150.88,162.31 E83.6 | E81.13 168.66,150.88 166.37,150.88 166.12,150.62 165.61,150.62 164.85,151.38 164.85,151.64 164.08,152.4 E81.1 162.31,152.65 v157.73,157.23 | v153.67,145.8 152.65,145.8 E84.6 | K2B3.1 169.93,137.92 168.91,138.94 168.91,140.46 169.93,141.48 K2A3.1 | v150.62,157.48 150.37,157.48 | 170.94,168.15 170.94,168.66 173.74,168.66 E74.1 175.51,169.16 179.07,172.72 185.17,172.72 185.17,169.16 E71.1 186.94,169.16 v187.96,169.16 | 170.94,168.15 170.43,167.64 E80.13 | v196.85,166.62 196.85,165.35 197.87,165.35 E68.4 | 222.25,169.67 222.25,168.66 224.54,166.37 E77.3 226.31,166.12 v227.33,166.12 | 222.25,169.67 222.25,175.26 219.96,177.55 E64.8 | v222,169.67 222.25,169.67 | v171.45,159.26 170.94,159.77 170.94,168.15
  Bottom 0.254: K2A3.1 169.42,142.49 168.4,143.51 165.1,143.51 163.58,145.03 154.43,145.03 v153.67,145.8 153.42,146.05 148.34,146.05 148.34,156.72 149.1,157.48 v150.62,157.48 157.48,157.48 v157.73,157.23 157.99,157.48 159.77,159.26 v171.45,159.26 | v187.96,169.16 194.31,169.16 v196.85,166.62 197.1,166.88 199.9,169.67 201.93,169.67 202.18,169.42 221.74,169.42 v222,169.67 | v227.33,166.12 228.09,165.35 242.57,165.35 U$12.K2
K8  (via drill 0.61)
  Top 0.254: E83.14 159,168.91 161.04,166.88 161.04,165.35 162.31,165.35 E80.4 164.08,164.85 165.35,164.85 165.35,162.05 165.61,161.8 165.61,160.02 166.62,159 170.43,159 171.2,158.24 173.23,158.24 173.23,162.05 173.74,162.56 E74.6 175.51,162.56 v176.53,162.56 | v227.33,167.39 226.31,167.39 E77.2 | v241.81,166.37 242.57,165.61 U$12.K1 | v214.63,165.86 214.63,162.81 213.61,162.81 E66.6 | v200.66,168.66 199.64,168.66 E68.1 | v194.31,164.59 194.31,162.81 193.29,162.81 E71.9
  Bottom 0.254: v241.81,166.37 228.35,166.37 v227.33,167.39 227.08,167.13 226.31,166.37 215.14,166.37 v214.63,165.86 214.38,166.12 200.66,166.12 | 200.66,166.12 v200.66,168.66 | 200.66,166.12 200.15,165.61 195.33,165.61 v194.31,164.59 194.06,164.34 188.47,164.34 186.69,162.56 v176.53,162.56
K9  (via drill 0.61)
  Top 0.254: 150.37,91.44 150.37,85.6 150.88,85.09 E105.2 | 150.37,91.44 150.37,96.27 150.88,96.27 E104.6 | E102.13 168.66,84.84 166.37,84.84 166.12,84.58 165.61,84.58 164.85,85.34 164.85,85.6 164.08,86.36 E102.1 162.31,86.61 v157.73,91.19 | v153.67,79.76 152.65,79.76 E105.6 | K2B4.1 169.93,71.88 168.91,72.9 168.91,74.42 169.93,75.44 K2A4.1 | v150.62,91.44 150.37,91.44 | 170.94,102.11 170.94,102.62 173.74,102.62 E95.1 175.51,103.12 179.07,106.68 185.17,106.68 185.17,103.12 E92.1 186.94,103.12 v187.96,103.12 | 170.94,102.11 170.43,101.6 E101.13 | v196.85,100.58 196.85,99.31 197.87,99.31 E89.4 | 222.25,103.63 222.25,102.62 224.54,100.33 E98.3 226.31,100.08 v227.33,100.08 | 222.25,103.63 222.25,109.22 219.96,111.51 E85.8 | v222,103.63 222.25,103.63 | v171.45,93.22 170.94,93.73 170.94,102.11
  Bottom 0.254: K2A4.1 169.42,76.45 168.4,77.47 165.1,77.47 163.58,78.99 154.43,78.99 v153.67,79.76 153.42,80.01 148.34,80.01 148.34,90.68 149.1,91.44 v150.62,91.44 157.48,91.44 v157.73,91.19 157.99,91.44 159.77,93.22 v171.45,93.22 | v187.96,103.12 194.31,103.12 v196.85,100.58 197.1,100.84 199.9,103.63 201.93,103.63 202.18,103.38 221.74,103.38 v222,103.63 | v227.33,100.08 228.09,99.31 242.57,99.31 U$15.K2
K10  (via drill 0.61)
  Top 0.254: E104.14 159,102.87 161.04,100.84 161.04,99.31 162.31,99.31 E101.4 164.08,98.81 165.35,98.81 165.35,96.01 165.61,95.76 165.61,93.98 166.62,92.96 170.43,92.96 171.2,92.2 173.23,92.2 173.23,96.01 173.74,96.52 E95.6 175.51,96.52 v176.53,96.52 | v227.33,101.35 226.31,101.35 E98.2 | v241.81,100.33 242.57,99.57 U$15.K1 | v214.63,99.82 214.63,96.77 213.61,96.77 E87.6 | v200.66,102.62 199.64,102.62 E89.1 | v194.31,98.55 194.31,96.77 193.29,96.77 E92.9
  Bottom 0.254: v241.81,100.33 228.35,100.33 v227.33,101.35 227.08,101.09 226.31,100.33 215.14,100.33 v214.63,99.82 214.38,100.08 200.66,100.08 | 200.66,100.08 v200.66,102.62 | 200.66,100.08 200.15,99.57 195.33,99.57 v194.31,98.55 194.06,98.3 188.47,98.3 186.69,96.52 v176.53,96.52
K11  (via drill 0.61)
  Top 0.254: 150.37,25.4 150.37,19.56 150.88,19.05 E126.2 | 150.37,25.4 150.37,30.23 150.88,30.23 E125.6 | E123.13 168.66,18.8 166.37,18.8 166.12,18.54 165.61,18.54 164.85,19.3 164.85,19.56 164.08,20.32 E123.1 162.31,20.57 v157.73,25.15 | v153.67,13.72 152.65,13.72 E126.6 | K2B5.1 169.93,5.84 168.91,6.86 168.91,8.38 169.93,9.4 K2A5.1 | v150.62,25.4 150.37,25.4 | 170.94,36.07 170.94,36.58 173.74,36.58 E116.1 175.51,37.08 179.07,40.64 185.17,40.64 185.17,37.08 E113.1 186.94,37.08 v187.96,37.08 | 170.94,36.07 170.43,35.56 E122.13 | v196.85,34.54 196.85,33.27 197.87,33.27 E110.4 | 222.25,37.59 222.25,36.58 224.54,34.29 E119.3 226.31,34.04 v227.33,34.04 | 222.25,37.59 222.25,43.18 219.96,45.47 E106.8 | 222.25,37.59 v222,37.59 | v171.45,27.18 170.94,27.69 170.94,36.07
  Bottom 0.254: K2A5.1 169.42,10.41 168.4,11.43 165.1,11.43 163.58,12.95 154.43,12.95 v153.67,13.72 153.42,13.97 148.34,13.97 148.34,24.64 149.1,25.4 v150.62,25.4 157.48,25.4 v157.73,25.15 157.99,25.4 159.77,27.18 v171.45,27.18 | v187.96,37.08 194.31,37.08 v196.85,34.54 197.1,34.8 199.9,37.59 201.93,37.59 202.18,37.34 221.74,37.34 v222,37.59 | v227.33,34.04 228.09,33.27 242.57,33.27 U$18.K2
K12  (via drill 0.61)
  Top 0.254: E125.14 159,36.83 161.04,34.8 161.04,33.27 162.31,33.27 E122.4 164.08,32.77 165.35,32.77 165.35,29.97 165.61,29.72 165.61,27.94 166.62,26.92 170.43,26.92 171.2,26.16 173.23,26.16 173.23,29.97 173.74,30.48 E116.6 175.51,30.48 v176.53,30.48 | v227.33,35.31 226.31,35.31 E119.2 | v241.81,34.29 242.57,33.53 U$18.K1 | v214.63,33.78 214.63,30.73 213.61,30.73 E108.6 | v200.66,36.58 199.64,36.58 E110.1 | v194.31,32.51 194.31,30.73 193.29,30.73 E113.9
  Bottom 0.254: v241.81,34.29 228.35,34.29 v227.33,35.31 227.08,35.05 226.31,34.29 215.14,34.29 v214.63,33.78 214.38,34.04 200.66,34.04 | 200.66,34.04 v200.66,36.58 | 200.66,34.04 200.15,33.53 195.33,33.53 v194.31,32.51 194.06,32.26 188.47,32.26 186.69,30.48 v176.53,30.48
L1  (via drill 0.61)
  Top 0.254: v29.21,30.73 30.23,30.73 E2.5 | v14.99,30.73 13.97,31.75 U$1.L1 | v39.37,30.99 41.4,33.02 41.4,40.13 42.93,41.66 E6.1 44.7,41.66 v44.7,37.59 | E17.5 94.23,30.23 95.25,30.23 95.25,29.97 97.54,27.69 E20.12 99.31,28.19 v100.33,28.19 | 61.21,26.67 58.67,26.67 E8.2 | 61.21,26.67 61.21,31.24 62.48,32.51 | 62.48,32.51 63.25,33.27 E11.8 | v108.2,23.62 108.2,7.62 v107.19,6.6 | v62.48,3.05 61.21,4.32 61.21,26.67 | v62.23,32.77 62.48,32.51
  Bottom 0.254: v14.99,30.73 v29.21,30.73 29.46,30.99 v39.37,30.99 | v100.33,28.19 100.58,28.45 103.38,28.45 v108.2,23.62 | v107.19,6.6 103.63,3.05 v62.48,3.05 | v44.7,37.59 54.1,37.59 58.93,32.77 v62.23,32.77
L2  (via drill 0.61)
  Top 0.254: v72.39,26.67 71.37,26.67 E11.2 69.6,26.42 68.58,26.42 67.56,25.4 67.56,24.89 68.33,24.13 v68.33,19.05 68.33,15.24 66.29,13.21 66.29,3.81 103.12,3.81 107.7,8.38 107.7,22.1 v107.19,22.61 | v80.01,26.67 81.03,26.67 E14.2 | v88.9,29.21 87.88,29.21 E17.11 | v102.87,30.23 103.89,30.23 E20.5 | v28.19,33.02 28.19,29.46 v29.21,29.46 30.23,29.46 E2.4 | v34.54,33.02 34.54,30.73 36.58,30.73 E5.10 | E8.5 56.9,30.23 55.88,30.23 v55.88,29.72 55.63,29.46 53.85,27.69 v53.85,18.8
  Bottom 0.254: v72.39,26.67 v80.01,26.67 80.26,26.92 89.92,26.92 89.92,28.19 v88.9,29.21 | v102.87,30.23 109.22,23.88 109.22,22.61 v107.19,22.61 | U$1.L2 13.97,33.02 v28.19,33.02 28.45,33.02 v34.54,33.02 | v55.88,29.72 55.63,29.46 v29.21,29.46 | v68.33,19.05 67.82,18.54 58.17,18.54 56.39,16.76 55.88,16.76 v53.85,18.8
L3  (via drill 0.61)
  Top 0.254: v72.39,92.71 71.37,92.71 E29.2 69.6,92.46 68.58,92.46 67.56,91.44 67.56,90.93 68.33,90.17 v68.33,85.09 68.33,81.28 66.29,79.25 66.29,69.85 103.12,69.85 107.7,74.42 107.7,88.14 v107.19,88.65 | v80.01,92.71 81.03,92.71 E32.2 | v88.9,95.25 87.88,95.25 E38.11 | v102.87,96.27 103.89,96.27 E41.5 | v28.19,99.06 28.19,95.5 v29.21,95.5 30.23,95.5 E35.4 | v34.54,99.06 34.54,96.77 36.58,96.77 E24.10 | E26.5 56.9,96.27 55.88,96.27 v55.88,95.76 55.63,95.5 53.85,93.73 v53.85,84.84
  Bottom 0.254: v72.39,92.71 v80.01,92.71 80.26,92.96 89.92,92.96 89.92,94.23 v88.9,95.25 | v102.87,96.27 109.22,89.92 109.22,88.65 v107.19,88.65 | U$6.L2 13.97,99.06 v28.19,99.06 28.45,99.06 v34.54,99.06 | v55.88,95.76 55.63,95.5 v29.21,95.5 | v68.33,85.09 67.82,84.58 58.17,84.58 56.39,82.8 55.88,82.8 v53.85,84.84
L4  (via drill 0.61)
  Top 0.254: v29.21,96.77 30.23,96.77 E35.5 | v14.99,96.77 13.97,97.79 U$6.L1 | v39.37,97.03 41.4,99.06 41.4,106.17 42.93,107.7 E23.1 44.7,107.7 v44.7,103.63 | E38.5 94.23,96.27 95.25,96.27 95.25,96.01 97.54,93.73 E41.12 99.31,94.23 v100.33,94.23 | 61.21,92.71 58.67,92.71 E26.2 | 61.21,92.71 61.21,97.28 62.48,98.55 | 62.48,98.55 63.25,99.31 E29.8 | v108.2,89.66 108.2,73.66 v107.19,72.64 | v62.48,69.09 61.21,70.36 61.21,92.71 | v62.23,98.81 62.48,98.55
  Bottom 0.254: v14.99,96.77 v29.21,96.77 29.46,97.03 v39.37,97.03 | v100.33,94.23 100.58,94.49 103.38,94.49 v108.2,89.66 | v107.19,72.64 103.63,69.09 v62.48,69.09 | v44.7,103.63 54.1,103.63 58.93,98.81 v62.23,98.81
L5  (via drill 0.61)
  Top 0.254: v72.39,158.75 71.37,158.75 E50.2 69.6,158.5 68.58,158.5 67.56,157.48 67.56,156.97 68.33,156.21 v68.33,151.13 68.33,147.32 66.29,145.29 66.29,135.89 103.12,135.89 107.7,140.46 107.7,154.18 v107.19,154.69 | v80.01,158.75 81.03,158.75 E53.2 | v88.9,161.29 87.88,161.29 E59.11 | v102.87,162.31 103.89,162.31 E62.5 | v28.19,165.1 28.19,161.54 v29.21,161.54 30.23,161.54 E56.4 | v34.54,165.1 34.54,162.81 36.58,162.81 E45.10 | E47.5 56.9,162.31 55.88,162.31 v55.88,161.8 55.63,161.54 53.85,159.77 v53.85,150.88
  Bottom 0.254: v72.39,158.75 v80.01,158.75 80.26,159 89.92,159 89.92,160.27 v88.9,161.29 | v102.87,162.31 109.22,155.96 109.22,154.69 v107.19,154.69 | U$9.L2 13.97,165.1 v28.19,165.1 28.45,165.1 v34.54,165.1 | v55.88,161.8 55.63,161.54 v29.21,161.54 | v68.33,151.13 67.82,150.62 58.17,150.62 56.39,148.84 55.88,148.84 v53.85,150.88
L6  (via drill 0.61)
  Top 0.254: v29.21,162.81 30.23,162.81 E56.5 | v14.99,162.81 13.97,163.83 U$9.L1 | v39.37,163.07 41.4,165.1 41.4,172.21 42.93,173.74 E44.1 44.7,173.74 v44.7,169.67 | E59.5 94.23,162.31 95.25,162.31 95.25,162.05 97.54,159.77 E62.12 99.31,160.27 v100.33,160.27 | 61.21,158.75 58.67,158.75 E47.2 | 61.21,158.75 61.21,163.32 62.48,164.59 | 62.48,164.59 63.25,165.35 E50.8 | v108.2,155.7 108.2,139.7 v107.19,138.68 | v62.48,135.13 61.21,136.4 61.21,158.75 | 62.48,164.59 v62.23,164.85
  Bottom 0.254: v14.99,162.81 v29.21,162.81 29.46,163.07 v39.37,163.07 | v100.33,160.27 100.58,160.53 103.38,160.53 v108.2,155.7 | v107.19,138.68 103.63,135.13 v62.48,135.13 | v44.7,169.67 54.1,169.67 58.93,164.85 v62.23,164.85
L7  (via drill 0.61)
  Top 0.254: v184.15,167.64 185.17,167.64 E71.2 186.94,167.89 187.96,167.89 188.98,168.91 188.98,169.42 188.21,170.18 v188.21,175.26 188.21,179.07 190.25,181.1 190.25,190.5 153.42,190.5 148.84,185.93 148.84,172.21 v149.35,171.7 | v176.53,167.64 175.51,167.64 E74.2 | v167.64,165.1 168.66,165.1 E80.11 | v153.67,164.08 152.65,164.08 E83.5 | v228.35,161.29 228.35,164.85 v227.33,164.85 226.31,164.85 E77.4 | v222,161.29 222,163.58 219.96,163.58 E66.10 | E68.5 199.64,164.08 200.66,164.08 v200.66,164.59 200.91,164.85 202.69,166.62 v202.69,175.51
  Bottom 0.254: v184.15,167.64 v176.53,167.64 176.28,167.39 166.62,167.39 166.62,166.12 v167.64,165.1 | v153.67,164.08 147.32,170.43 147.32,171.7 v149.35,171.7 | U$12.L2 242.57,161.29 v228.35,161.29 228.09,161.29 v222,161.29 | v200.66,164.59 200.91,164.85 v227.33,164.85 | v188.21,175.26 188.72,175.77 198.37,175.77 200.15,177.55 200.66,177.55 v202.69,175.51
L8  (via drill 0.61)
  Top 0.254: v227.33,163.58 226.31,163.58 E77.5 | v241.55,163.58 242.57,162.56 U$12.L1 | v217.17,163.32 215.14,161.29 215.14,154.18 213.61,152.65 E65.1 211.84,152.65 v211.84,156.72 | E80.5 162.31,164.08 161.29,164.08 161.29,164.34 159,166.62 E83.12 157.23,166.12 v156.21,166.12 | 195.33,167.64 197.87,167.64 E68.2 | 195.33,167.64 195.33,163.07 194.06,161.8 | 194.06,161.8 193.29,161.04 E71.8 | v148.34,170.69 148.34,186.69 v149.35,187.71 | v194.06,191.26 195.33,189.99 195.33,167.64 | 194.06,161.8 v194.31,161.54
  Bottom 0.254: v241.55,163.58 v227.33,163.58 227.08,163.32 v217.17,163.32 | v156.21,166.12 155.96,165.86 153.16,165.86 v148.34,170.69 | v149.35,187.71 152.91,191.26 v194.06,191.26 | v211.84,156.72 202.44,156.72 197.61,161.54 v194.31,161.54
L9  (via drill 0.61)
  Top 0.254: v184.15,101.6 185.17,101.6 E92.2 186.94,101.85 187.96,101.85 188.98,102.87 188.98,103.38 188.21,104.14 v188.21,109.22 188.21,113.03 190.25,115.06 190.25,124.46 153.42,124.46 148.84,119.89 148.84,106.17 v149.35,105.66 | v176.53,101.6 175.51,101.6 E95.2 | v167.64,99.06 168.66,99.06 E101.11 | v153.67,98.04 152.65,98.04 E104.5 | v228.35,95.25 228.35,98.81 v227.33,98.81 226.31,98.81 E98.4 | v222,95.25 222,97.54 219.96,97.54 E87.10 | E89.5 199.64,98.04 200.66,98.04 v200.66,98.55 200.91,98.81 202.69,100.58 v202.69,109.47
  Bottom 0.254: v184.15,101.6 v176.53,101.6 176.28,101.35 166.62,101.35 166.62,100.08 v167.64,99.06 | v153.67,98.04 147.32,104.39 147.32,105.66 v149.35,105.66 | U$15.L2 242.57,95.25 v228.35,95.25 228.09,95.25 v222,95.25 | v200.66,98.55 200.91,98.81 v227.33,98.81 | v188.21,109.22 188.72,109.73 198.37,109.73 200.15,111.51 200.66,111.51 v202.69,109.47
L10  (via drill 0.61)
  Top 0.254: v227.33,97.54 226.31,97.54 E98.5 | v241.55,97.54 242.57,96.52 U$15.L1 | v217.17,97.28 215.14,95.25 215.14,88.14 213.61,86.61 E86.1 211.84,86.61 v211.84,90.68 | E101.5 162.31,98.04 161.29,98.04 161.29,98.3 159,100.58 E104.12 157.23,100.08 v156.21,100.08 | 195.33,101.6 197.87,101.6 E89.2 | 195.33,101.6 195.33,97.03 194.06,95.76 | 194.06,95.76 193.29,95 E92.8 | v148.34,104.65 148.34,120.65 v149.35,121.67 | v194.06,125.22 195.33,123.95 195.33,101.6 | 194.06,95.76 v194.31,95.5
  Bottom 0.254: v241.55,97.54 v227.33,97.54 227.08,97.28 v217.17,97.28 | v156.21,100.08 155.96,99.82 153.16,99.82 v148.34,104.65 | v149.35,121.67 152.91,125.22 v194.06,125.22 | v211.84,90.68 202.44,90.68 197.61,95.5 v194.31,95.5
L11  (via drill 0.61)
  Top 0.254: v184.15,35.56 185.17,35.56 E113.2 186.94,35.81 187.96,35.81 188.98,36.83 188.98,37.34 188.21,38.1 v188.21,43.18 188.21,46.99 190.25,49.02 190.25,58.42 153.42,58.42 148.84,53.85 148.84,40.13 v149.35,39.62 | v176.53,35.56 175.51,35.56 E116.2 | v167.64,33.02 168.66,33.02 E122.11 | v153.67,32 152.65,32 E125.5 | v228.35,29.21 228.35,32.77 v227.33,32.77 226.31,32.77 E119.4 | v222,29.21 222,31.5 219.96,31.5 E108.10 | E110.5 199.64,32 200.66,32 v200.66,32.51 200.91,32.77 202.69,34.54 v202.69,43.43
  Bottom 0.254: v184.15,35.56 v176.53,35.56 176.28,35.31 166.62,35.31 166.62,34.04 v167.64,33.02 | v153.67,32 147.32,38.35 147.32,39.62 v149.35,39.62 | U$18.L2 242.57,29.21 v228.35,29.21 228.09,29.21 v222,29.21 | v200.66,32.51 200.91,32.77 v227.33,32.77 | v188.21,43.18 188.72,43.69 198.37,43.69 200.15,45.47 200.66,45.47 v202.69,43.43
L12  (via drill 0.61)
  Top 0.254: v227.33,31.5 226.31,31.5 E119.5 | v241.55,31.5 242.57,30.48 U$18.L1 | v217.17,31.24 215.14,29.21 215.14,22.1 213.61,20.57 E107.1 211.84,20.57 v211.84,24.64 | E122.5 162.31,32 161.29,32 161.29,32.26 159,34.54 E125.12 157.23,34.04 v156.21,34.04 | 195.33,35.56 197.87,35.56 E110.2 | 195.33,35.56 195.33,30.99 194.06,29.72 | 194.06,29.72 193.29,28.96 E113.8 | v148.34,38.61 148.34,54.61 v149.35,55.63 | v194.06,59.18 195.33,57.91 195.33,35.56 | v194.31,29.46 194.06,29.72
  Bottom 0.254: v241.55,31.5 v227.33,31.5 227.08,31.24 v217.17,31.24 | v156.21,34.04 155.96,33.78 153.16,33.78 v148.34,38.61 | v149.35,55.63 152.91,59.18 v194.06,59.18 | v211.84,24.64 202.44,24.64 197.61,29.46 v194.31,29.46
M1  (via drill 0.61)
  Top 0.254: E20.13 99.31,26.92 101.35,26.92 101.35,32.26 92.96,40.64 91.44,40.64 v91.44,37.08 91.44,32.77 92.46,31.75 E17.6 | v29.46,34.04 29.46,32 30.23,32 E2.6 32,31.75 32.51,31.24 32.51,29.97 v35.56,26.92 | v14.73,34.29 13.97,35.05 U$1.M1 | v45.72,35.05 v45.72,42.93 44.7,42.93 E6.2 | v49.53,26.92 50.55,26.92 E8.13 | v62.23,43.18 63.25,43.18 E12.13 | E15.12 74.68,44.2 v73.66,44.2 73.91,43.94 73.91,39.62 v75.18,38.35
  Bottom 0.254: v14.73,34.29 29.21,34.29 v29.46,34.04 29.72,34.29 44.96,34.29 v45.72,35.05 | v35.56,26.92 v49.53,26.92 | v45.72,42.93 61.98,42.93 v62.23,43.18 62.48,43.43 63.25,44.2 v73.66,44.2 | v91.44,37.08 91.19,37.34 76.2,37.34 v75.18,38.35
M2  (via drill 0.61)
  Top 0.254: v83.82,27.94 82.8,27.94 E14.3 | E17.12 87.88,27.94 v88.9,27.94 89.15,28.19 v90.17,29.21 | v72.39,28.45 72.39,28.96 71.37,28.96 E11.4 69.6,29.21 67.56,31.24 67.56,33.78 61.98,33.78 61.21,33.02 61.21,32 58.67,32 E8.6 56.9,31.75 v55.88,31.75 | v100.33,30.73 99.31,30.73 E20.10 | v22.86,35.31 v22.86,32 23.88,32 E2.9 | v35.56,32 36.58,32 E5.9
  Bottom 0.254: v88.9,27.94 v83.82,27.94 83.57,28.19 72.64,28.19 v72.39,28.45 | v100.33,30.73 99.31,31.75 92.71,31.75 v90.17,29.21 | v22.86,35.31 13.97,35.31 U$1.M2 | v22.86,32 v35.56,32 35.81,32 55.63,32 v55.88,31.75
M3  (via drill 0.61)
  Top 0.254: v83.82,93.98 82.8,93.98 E32.3 | E38.12 87.88,93.98 v88.9,93.98 89.15,94.23 v90.17,95.25 | v72.39,94.49 72.39,95 71.37,95 E29.4 69.6,95.25 67.56,97.28 67.56,99.82 61.98,99.82 61.21,99.06 61.21,98.04 58.67,98.04 E26.6 56.9,97.79 v55.88,97.79 | v100.33,96.77 99.31,96.77 E41.10 | v22.86,101.35 v22.86,98.04 23.88,98.04 E35.9 | v35.56,98.04 36.58,98.04 E24.9
  Bottom 0.254: v88.9,93.98 v83.82,93.98 83.57,94.23 72.64,94.23 v72.39,94.49 | v100.33,96.77 99.31,97.79 92.71,97.79 v90.17,95.25 | v22.86,101.35 13.97,101.35 U$6.M2 | v22.86,98.04 v35.56,98.04 35.81,98.04 55.63,98.04 v55.88,97.79
M4  (via drill 0.61)
  Top 0.254: E41.13 99.31,92.96 101.35,92.96 101.35,98.3 92.96,106.68 91.44,106.68 v91.44,103.12 91.44,98.81 92.46,97.79 E38.6 | v29.46,100.08 29.46,98.04 30.23,98.04 E35.6 32,97.79 32.51,97.28 32.51,96.01 v35.56,92.96 | v14.73,100.33 13.97,101.09 U$6.M1 | v45.72,101.09 v45.72,108.97 44.7,108.97 E23.2 | v49.53,92.96 50.55,92.96 E26.13 | v62.23,109.22 63.25,109.22 E30.13 | E33.12 74.68,110.24 v73.66,110.24 73.91,109.98 73.91,105.66 v75.18,104.39
  Bottom 0.254: v14.73,100.33 29.21,100.33 v29.46,100.08 29.72,100.33 44.96,100.33 v45.72,101.09 | v35.56,92.96 v49.53,92.96 | v45.72,108.97 61.98,108.97 v62.23,109.22 62.48,109.47 63.25,110.24 v73.66,110.24 | v91.44,103.12 91.19,103.38 76.2,103.38 v75.18,104.39
M5  (via drill 0.61)
  Top 0.254: v83.82,160.02 82.8,160.02 E53.3 | E59.12 87.88,160.02 v88.9,160.02 89.15,160.27 v90.17,161.29 | v72.39,160.53 72.39,161.04 71.37,161.04 E50.4 69.6,161.29 67.56,163.32 67.56,165.86 61.98,165.86 61.21,165.1 61.21,164.08 58.67,164.08 E47.6 56.9,163.83 v55.88,163.83 | v100.33,162.81 99.31,162.81 E62.10 | v22.86,167.39 v22.86,164.08 23.88,164.08 E56.9 | v35.56,164.08 36.58,164.08 E45.9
